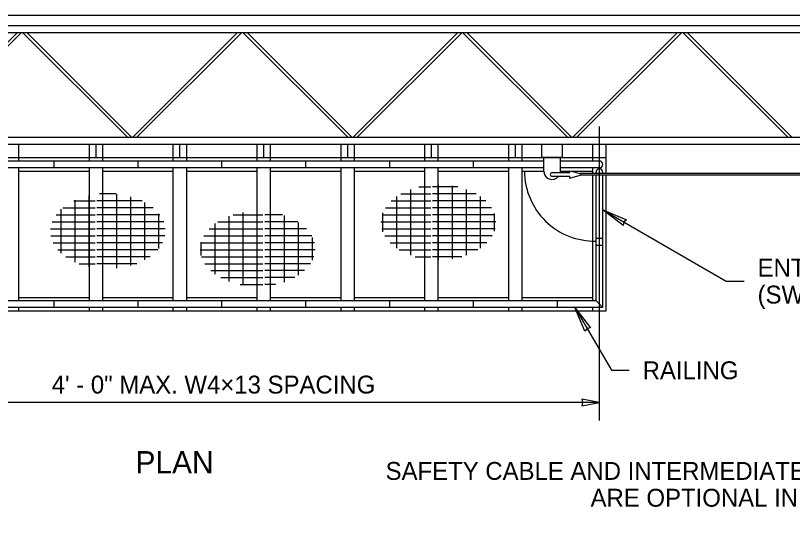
# Model space of a CAD drawing. Extents: x 99862 to 103151, y 100000 to 105076.
# Drawn here: x 101035 to 101730, y 101626 to 102076 of the extents above; entities that cross this region are included whole.
import ezdxf

# ---------------------------------------------------------------- set-up
doc = ezdxf.new("R2010")
doc.units = 0
for name, color, linetype in [('Level 1', 7, 'Continuous'), ('Level 11', 7, 'Continuous'), ('Level 15', 7, 'Continuous'), ('Level 18', 7, 'Continuous'), ('Level 2', 7, 'Continuous'), ('Level 20', 7, 'Continuous'), ('Level 23', 7, 'Continuous'), ('Level 26', 7, 'Continuous'), ('Level 7', 7, 'Continuous')]:
    doc.layers.add(name, color=color, linetype=linetype)

msp = doc.modelspace()

# ---------------------------------------------------------------- linework, layer by layer
at = {"layer": 'Level 1'}
msp.add_lwpolyline([(99862, 99999.5), (103151, 99999.5), (103151, 102075.5), (99862, 102075.5)], close=True, dxfattribs=at)
at = {"layer": 'Level 11'}
for p, q in [((101507.27, 101936.34), (101507.27, 101948.32)), ((101522.17, 101936.34), (101522.17, 101948.32)), ((101530.66, 101934.98), (101530.66, 101936.66)), ((101530.66, 101936.66), (101540, 101934.17)), ((101514.82, 101934.98), (101530.66, 101934.98)), ((101514.82, 101931.66), (101530.66, 101931.66)), ((101530.66, 101930.02), (101540, 101932.51)), ((101530.66, 101930.02), (101530.66, 101931.66)), ((101540, 101934.17), (101540, 101932.51)), ((102167.43, 101934.17), (101540, 101934.17)), ((102167.43, 101932.51), (101540, 101932.51))]:
    msp.add_line(p, q, dxfattribs=at)
for centre, radius, start, end in [((101514.72, 101936.34), 7.45, 180, 321.06769), ((101514.72, 101936.34), 7.45, 349.46919, 0), ((101514.82, 101933.32), 1.66, 90, 270)]:
    msp.add_arc(centre, radius, start, end, dxfattribs=at)
at = {"layer": 'Level 15'}
for p, q in [((101557.05, 101713.28), (101557.05, 101976.32)), ((101560.05, 101901.56), (101670.48, 101837.81)), ((101670.48, 101837.81), (101686.48, 101837.81)), ((101535.23, 101814.36), (101567.73, 101758.07)), ((101567.73, 101758.07), (101583.73, 101758.07)), ((101557.05, 101729.28), (100876.05, 101729.28))]:
    msp.add_line(p, q, dxfattribs=at)
for points in [[(101560.06, 101901.56), (101581.32, 101892.73), (101578.91, 101890.68), (101578.33, 101887.56)], [(101535.23, 101814.36), (101549.23, 101796.08), (101546.12, 101795.51), (101544.06, 101793.1)], [(101557.05, 101729.28), (101541.32, 101732.36), (101542.05, 101729.28), (101541.32, 101726.19)]]:
    msp.add_lwpolyline(points, close=True, dxfattribs=at)
at = {"layer": 'Level 18'}
for p, q in [((101038.05, 101948.32), (101038.05, 101960.32)), ((101101.05, 101948.32), (101101.05, 101960.32)), ((101113.05, 101948.32), (101113.05, 101960.32)), ((101176.05, 101948.32), (101176.05, 101960.32)), ((101188.05, 101948.32), (101188.05, 101960.32)), ((101251.05, 101948.32), (101251.05, 101960.32)), ((101263.05, 101948.32), (101263.05, 101960.32)), ((101326.05, 101948.32), (101326.05, 101960.32)), ((101338.05, 101948.32), (101338.05, 101960.32)), ((101401.05, 101948.32), (101401.05, 101960.32)), ((101413.05, 101948.32), (101413.05, 101960.32)), ((101476.05, 101948.32), (101476.05, 101960.32)), ((101488.05, 101948.32), (101488.05, 101960.32)), ((101551.05, 101948.32), (101551.05, 101960.32)), ((101563.05, 101948.32), (101563.05, 101960.32))]:
    msp.add_line(p, q, dxfattribs=at)
at = {"layer": 'Level 2'}
for p, q in [((100876.05, 101948.32), (101563.05, 101948.32)), ((101507.27, 101945.28), (100882.02, 101945.28)), ((101038.05, 101945.28), (101038.05, 101948.32)), ((101069.55, 101939.28), (101069.55, 101945.28)), ((101101.05, 101945.28), (101101.05, 101948.32)), ((101113.05, 101945.28), (101113.05, 101948.32)), ((101144.55, 101939.28), (101144.55, 101945.28)), ((101176.05, 101945.28), (101176.05, 101948.32)), ((101188.05, 101945.28), (101188.05, 101948.32)), ((101219.55, 101939.28), (101219.55, 101945.28)), ((101251.05, 101945.28), (101251.05, 101948.32)), ((101263.05, 101945.28), (101263.05, 101948.32)), ((101294.55, 101939.28), (101294.55, 101945.28)), ((101326.05, 101945.28), (101326.05, 101948.32)), ((101338.05, 101945.28), (101338.05, 101948.32)), ((101369.55, 101939.28), (101369.55, 101945.28)), ((101401.05, 101945.28), (101401.05, 101948.32)), ((101413.05, 101945.28), (101413.05, 101948.32)), ((101444.55, 101939.28), (101444.55, 101945.28)), ((101476.05, 101945.28), (101476.05, 101948.32)), ((101488.05, 101945.28), (101488.05, 101948.32)), ((101557.09, 101945.28), (101522.17, 101945.28)), ((101551.05, 101945.28), (101551.05, 101948.32)), ((101563.05, 101934.17), (101563.05, 101948.32)), ((101507.27, 101939.28), (100882.02, 101939.28)), ((101038.05, 101820.36), (101038.05, 101939.28)), ((101038.05, 101936.32), (101101.05, 101936.32)), ((101101.05, 101820.36), (101101.05, 101939.28)), ((101113.05, 101820.36), (101113.05, 101939.28)), ((101113.05, 101936.32), (101176.05, 101936.32)), ((101176.05, 101820.36), (101176.05, 101939.28)), ((101188.05, 101820.36), (101188.05, 101939.28)), ((101188.05, 101936.32), (101251.05, 101936.32)), ((101251.05, 101820.36), (101251.05, 101939.28)), ((101263.05, 101820.36), (101263.05, 101939.28)), ((101263.05, 101936.32), (101326.05, 101936.32)), ((101326.05, 101820.36), (101326.05, 101939.28)), ((101338.05, 101820.36), (101338.05, 101939.28)), ((101338.05, 101936.32), (101401.05, 101936.32)), ((101401.05, 101820.36), (101401.05, 101939.28)), ((101413.05, 101820.36), (101413.05, 101939.28)), ((101413.05, 101936.32), (101476.05, 101936.32)), ((101476.05, 101820.36), (101476.05, 101939.28)), ((101488.05, 101820.36), (101488.05, 101939.28)), ((101488.05, 101936.32), (101507.27, 101936.32)), ((101557.09, 101939.28), (101522.17, 101939.28)), ((101522.17, 101936.32), (101530.66, 101936.32)), ((101531.94, 101936.32), (101551.05, 101936.32)), ((101551.05, 101934.17), (101551.05, 101939.28)), ((101551.05, 101820.36), (101551.05, 101932.51)), ((101554.05, 101934.17), (101554.05, 101935.38)), ((101554.05, 101820.36), (101554.05, 101932.51)), ((101560.05, 101934.17), (101560.05, 101935.38)), ((101560.05, 101814.36), (101560.05, 101932.51)), ((101563.05, 101811.32), (101563.05, 101932.51)), ((101554.05, 101876.35), (101560.05, 101876.35)), ((101554.05, 101870.08), (101560.05, 101870.08)), ((101554.05, 101820.36), (100885.04, 101820.36)), ((101038.05, 101823.32), (101101.05, 101823.32)), ((101069.55, 101814.36), (101069.55, 101820.36)), ((101113.05, 101823.32), (101176.05, 101823.32)), ((101144.55, 101814.36), (101144.55, 101820.36)), ((101188.05, 101823.32), (101251.05, 101823.32)), ((101219.55, 101814.36), (101219.55, 101820.36)), ((101263.05, 101823.32), (101326.05, 101823.32)), ((101294.55, 101814.36), (101294.55, 101820.36)), ((101338.05, 101823.32), (101401.05, 101823.32)), ((101369.55, 101814.36), (101369.55, 101820.36)), ((101413.05, 101823.32), (101476.05, 101823.32)), ((101444.55, 101814.36), (101444.55, 101820.36)), ((101488.05, 101823.32), (101551.05, 101823.32)), ((101519.55, 101814.36), (101519.55, 101820.36)), ((101560.05, 101814.36), (101554.05, 101820.36)), ((100876.05, 101811.32), (101563.05, 101811.32)), ((101560.05, 101814.36), (100879.04, 101814.36)), ((101038.05, 101811.32), (101038.05, 101814.36)), ((101101.05, 101811.32), (101101.05, 101814.36)), ((101113.05, 101811.32), (101113.05, 101814.36)), ((101176.05, 101811.32), (101176.05, 101814.36)), ((101188.05, 101811.32), (101188.05, 101814.36)), ((101251.05, 101811.32), (101251.05, 101814.36)), ((101263.05, 101811.32), (101263.05, 101814.36)), ((101326.05, 101811.32), (101326.05, 101814.36)), ((101338.05, 101811.32), (101338.05, 101814.36)), ((101401.05, 101811.32), (101401.05, 101814.36)), ((101413.05, 101811.32), (101413.05, 101814.36)), ((101476.05, 101811.32), (101476.05, 101814.36)), ((101488.05, 101811.32), (101488.05, 101814.36)), ((101551.05, 101811.32), (101551.05, 101814.36))]:
    msp.add_line(p, q, dxfattribs=at)
for centre, radius, start, end in [((101557.09, 101942.28), 3, 270, 90), ((101552.62, 101936.18), 62.5, 180, 271.31491), ((101557.05, 101935.38), 3, 0, 180)]:
    msp.add_arc(centre, radius, start, end, dxfattribs=at)
at = {"layer": 'Level 23'}
for p, q in [((101026.05, 101960.32), (101038.05, 101960.32)), ((101101.05, 101960.32), (101113.05, 101960.32)), ((101107.05, 101948.32), (101107.05, 101960.32)), ((101176.05, 101960.32), (101188.05, 101960.32)), ((101182.05, 101948.32), (101182.05, 101960.32)), ((101251.05, 101960.32), (101263.05, 101960.32)), ((101257.05, 101948.32), (101257.05, 101960.32)), ((101326.05, 101960.32), (101338.05, 101960.32)), ((101332.05, 101948.32), (101332.05, 101960.32)), ((101401.05, 101960.32), (101413.05, 101960.32)), ((101407.05, 101948.32), (101407.05, 101960.32)), ((101476.05, 101960.32), (101488.05, 101960.32)), ((101482.05, 101948.32), (101482.05, 101960.32)), ((101551.05, 101960.32), (101563.05, 101960.32)), ((101557.05, 101948.32), (101557.05, 101960.32)), ((101026.05, 101948.32), (101038.05, 101948.32)), ((101101.05, 101948.32), (101113.05, 101948.32)), ((101176.05, 101948.32), (101188.05, 101948.32)), ((101251.05, 101948.32), (101263.05, 101948.32)), ((101326.05, 101948.32), (101338.05, 101948.32)), ((101401.05, 101948.32), (101413.05, 101948.32)), ((101476.05, 101948.32), (101488.05, 101948.32)), ((101551.05, 101948.32), (101563.05, 101948.32))]:
    msp.add_line(p, q, dxfattribs=at)
msp.add_lwpolyline([(101505.72, 101960.32), (101523.72, 101960.32), (101523.72, 101948.32), (101505.72, 101948.32)], close=True, dxfattribs=at)
at = {"layer": 'Level 26'}
for p, q in [((101395.76, 101922.09), (101406.27, 101922.09)), ((101400.95, 101857.76), (101400.95, 101923.11)), ((101430.58, 101922.09), (101407.83, 101922.09)), ((101413.15, 101856.8), (101413.15, 101924.07)), ((101425.65, 101857.8), (101425.65, 101923.07)), ((101124.98, 101915.85), (101110.21, 101915.85)), ((101113.15, 101849.05), (101113.15, 101916.07)), ((101125.65, 101849.34), (101125.65, 101915.78)), ((101379.48, 101915.85), (101406.27, 101915.85)), ((101388.45, 101860.94), (101388.45, 101919.93)), ((101446.87, 101915.85), (101407.83, 101915.85)), ((101438.14, 101861.03), (101438.14, 101919.84)), ((101087.03, 101909.61), (101106.27, 101909.61)), ((101088.45, 101854.85), (101088.45, 101910.27)), ((101100.95, 101850.73), (101100.95, 101914.38)), ((101148.17, 101909.61), (101107.83, 101909.61)), ((101138.14, 101851.72), (101138.14, 101913.39)), ((101150.64, 101856.78), (101150.64, 101908.33)), ((101370.91, 101909.61), (101406.27, 101909.61)), ((101375.96, 101867.22), (101375.96, 101913.65)), ((101455.43, 101909.61), (101407.83, 101909.61)), ((101450.64, 101867.4), (101450.64, 101913.48)), ((101075.96, 101862.82), (101075.96, 101902.3)), ((101077.19, 101903.37), (101106.27, 101903.37)), ((101158, 101903.37), (101107.83, 101903.37)), ((101365.7, 101903.37), (101406.27, 101903.37)), ((101460.65, 101903.37), (101407.83, 101903.37)), ((101071.24, 101897.13), (101106.27, 101897.13)), ((101163.95, 101897.13), (101107.83, 101897.13)), ((101163.13, 101866.93), (101163.13, 101898.19)), ((101225.96, 101837.58), (101225.96, 101895.88)), ((101229.58, 101897.13), (101256.27, 101897.13)), ((101238.45, 101834.21), (101238.45, 101899.25)), ((101250.95, 101833.1), (101250.95, 101900.36)), ((101273.62, 101897.13), (101257.83, 101897.13)), ((101263.15, 101833.95), (101263.15, 101899.51)), ((101275.65, 101837), (101275.65, 101896.46)), ((101362.77, 101897.13), (101406.27, 101897.13)), ((101363.46, 101881.82), (101363.46, 101899.05)), ((101463.57, 101897.13), (101407.83, 101897.13)), ((101463.13, 101882.47), (101463.13, 101898.4)), ((101067.77, 101890.89), (101106.27, 101890.89)), ((101167.49, 101890.89), (101107.83, 101890.89)), ((101213.46, 101844.17), (101213.46, 101889.29)), ((101215.82, 101890.89), (101256.27, 101890.89)), ((101287.39, 101890.89), (101257.83, 101890.89)), ((101288.14, 101843.06), (101288.14, 101890.4)), ((101361.75, 101890.89), (101406.27, 101890.89)), ((101464.59, 101890.89), (101407.83, 101890.89)), ((101066.27, 101884.65), (101106.27, 101884.65)), ((101168.93, 101884.65), (101107.83, 101884.65)), ((101208.08, 101884.65), (101256.27, 101884.65)), ((101295.13, 101884.65), (101257.83, 101884.65)), ((101362.51, 101884.65), (101406.27, 101884.65)), ((101463.83, 101884.65), (101407.83, 101884.65)), ((101066.57, 101878.41), (101106.27, 101878.41)), ((101168.63, 101878.41), (101107.83, 101878.41)), ((101203.37, 101878.41), (101256.27, 101878.41)), ((101299.83, 101878.41), (101257.83, 101878.41)), ((101300.64, 101856.59), (101300.64, 101876.87)), ((101365.15, 101878.41), (101406.27, 101878.41)), ((101461.2, 101878.41), (101407.83, 101878.41)), ((101068.69, 101872.17), (101106.27, 101872.17)), ((101166.51, 101872.17), (101107.83, 101872.17)), ((101200.85, 101872.17), (101256.27, 101872.17)), ((101200.97, 101860.86), (101200.97, 101872.6)), ((101302.35, 101872.17), (101257.83, 101872.17)), ((101369.99, 101872.17), (101406.27, 101872.17)), ((101456.35, 101872.17), (101407.83, 101872.17)), ((101072.9, 101865.93), (101106.27, 101865.93)), ((101079.89, 101859.69), (101106.27, 101859.69)), ((101162.3, 101865.93), (101107.83, 101865.93)), ((101155.3, 101859.69), (101107.83, 101859.69)), ((101200.19, 101865.93), (101256.27, 101865.93)), ((101201.32, 101859.69), (101256.27, 101859.69)), ((101303.01, 101865.93), (101257.83, 101865.93)), ((101301.89, 101859.69), (101257.83, 101859.69)), ((101377.95, 101865.93), (101406.27, 101865.93)), ((101392.33, 101859.69), (101406.27, 101859.69)), ((101448.39, 101865.93), (101407.83, 101865.93)), ((101434.01, 101859.69), (101407.83, 101859.69)), ((101091.84, 101853.45), (101106.27, 101853.45)), ((101143.36, 101853.45), (101107.83, 101853.45)), ((101204.36, 101853.45), (101256.27, 101853.45)), ((101298.85, 101853.45), (101257.83, 101853.45)), ((101209.73, 101847.21), (101256.27, 101847.21)), ((101293.48, 101847.21), (101257.83, 101847.21)), ((101218.54, 101840.97), (101256.27, 101840.97)), ((101284.66, 101840.97), (101257.83, 101840.97)), ((101235.78, 101834.73), (101256.27, 101834.73)), ((101267.43, 101834.73), (101257.83, 101834.73))]:
    msp.add_line(p, q, dxfattribs=at)
at = {"layer": 'Level 7'}
for p, q in [((100622.05, 102066.57), (102322.56, 102066.57)), ((100622.05, 102060.32), (102322.56, 102060.32)), ((101036.69, 102060.32), (100942.94, 101966.57)), ((101040.37, 102060.32), (100946.62, 101966.57)), ((101041.41, 102060.32), (101135.16, 101966.57)), ((101045.09, 102060.32), (101138.84, 101966.57)), ((101233.64, 102060.32), (101139.89, 101966.57)), ((101237.32, 102060.32), (101143.57, 101966.57)), ((101238.36, 102060.32), (101332.11, 101966.57)), ((101242.04, 102060.32), (101335.79, 101966.57)), ((101430.58, 102060.32), (101336.83, 101966.57)), ((101434.27, 102060.32), (101340.52, 101966.57)), ((101434.77, 102060.32), (101528.52, 101966.57)), ((101438.45, 102060.32), (101532.2, 101966.57)), ((101626.99, 102060.32), (101533.24, 101966.57)), ((101630.67, 102060.32), (101536.92, 101966.57)), ((101631.72, 102060.32), (101725.47, 101966.57)), ((101635.4, 102060.32), (101729.15, 101966.57)), ((100622.05, 101966.57), (102322.56, 101966.57)), ((100622.05, 101960.32), (102322.56, 101960.32))]:
    msp.add_line(p, q, dxfattribs=at)

# ---------------------------------------------------------------- texts
at = {"layer": 'Level 20'}
for s, height, p in [('ENTRANCE TO WALKWAY', 16, (101698.49, 101841.81)), ('(SWING GATE INSIDE ONLY)', 16, (101698.49, 101817.81)), ('RAILING', 16, (101595.74, 101750.07)), ('4\' - 0" MAX. W4×13 SPACING', 16, (101067.37, 101737.28)), ('PLAN', 20, (101142.29, 101665.75)), ('SAFETY CABLE AND INTERMEDIATE SUPPORT', 16, (101365.92, 101660.02)), ('ARE OPTIONAL IN THIS ZONE', 16, (101549.17, 101636.02))]:
    msp.add_text(s, height=height, dxfattribs=at).set_placement(p)

doc.saveas('drawing.dxf')
